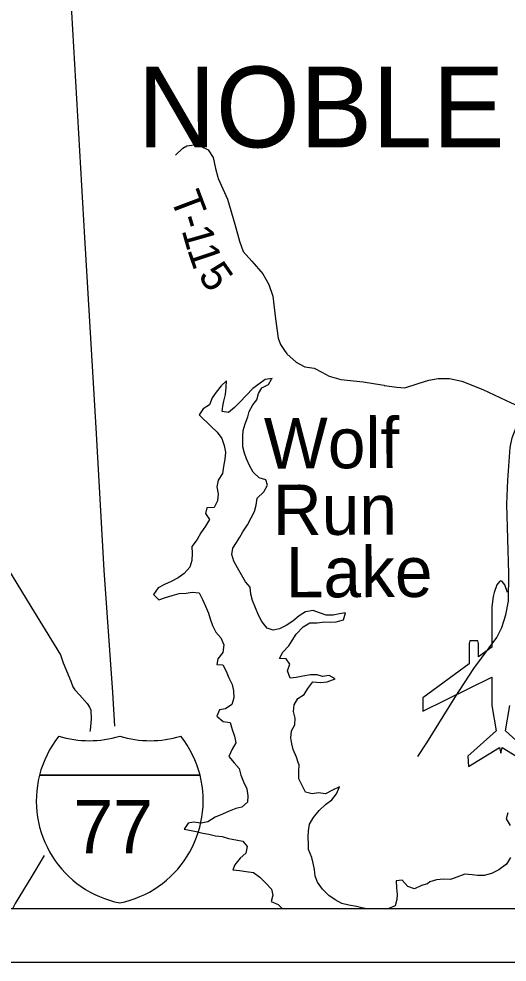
# Model space of a CAD drawing. Extents: x -22 to 431, y -18 to 160.
# Drawn here: x 3.524 to 4.438, y 14 to 15.768 of the extents above; entities that cross this region are included whole.
import ezdxf

# ---------------------------------------------------------------- set-up
doc = ezdxf.new("R2010")
doc.units = 0
for name, color, linetype in [('GM_X_Adjacent_County_Text', 7, 'Continuous'), ('GM_X_Airport_Location_Class_2', 7, 'Continuous'), ('GM_X_Airport_Text_Class_2', 7, 'Continuous'), ('GM_X_City_Street_Text', 7, 'Continuous'), ('GM_X_County_Road', 7, 'Continuous'), ('GM_X_County_Road_Text', 7, 'Continuous'), ('GM_X_Minor_River_Text', 7, 'Continuous'), ('GM_X_Rail_Line', 7, 'Continuous'), ('GM_X_Rail_Line_Text', 7, 'Continuous'), ('GM_X_Section', 7, 'Continuous'), ('GM_X_Township_Subdivision', 7, 'Continuous'), ('GM_X_US_Location', 7, 'Continuous')]:
    doc.layers.add(name, color=color, linetype=linetype)

msp = doc.modelspace()

# ---------------------------------------------------------------- linework, layer by layer
at = {"layer": 'GM_X_Adjacent_County_Text'}
msp.add_lwpolyline([(4.2712, 14.3856), (4.288, 14.4108), (4.341, 14.4966), (4.3758, 14.5505), (4.4185, 14.6086), (4.4283, 14.6269), (4.4359, 14.6508), (4.4404, 14.6766), (4.4411, 14.7286), (4.4376, 14.8583), (4.4394, 14.9035), (4.4439, 14.9642), (4.4477, 14.9824), (4.4552, 15.0022), (4.4628, 15.0181), (4.4707, 15.0352), (4.479, 15.0432), (4.4893, 15.0557), (4.5014, 15.0709), (4.512, 15.0895), (4.5225, 15.1127), (4.5274, 15.1263)], dxfattribs=at)
at = {"layer": 'GM_X_County_Road'}
msp.add_lwpolyline([(3.8174, 15.5124), (3.8309, 15.5254), (3.8388, 15.5296), (3.8521, 15.5316), (3.8653, 15.5287), (3.8786, 15.522), (3.8878, 15.508), (3.8921, 15.4872), (3.8964, 15.4709), (3.8974, 15.4687), (3.8975, 15.4685)], dxfattribs=at)
at = {"layer": 'GM_X_Minor_River_Text'}
for points in [[(3.8975, 15.4685), (3.9145, 15.43), (3.9281, 15.3831), (3.937, 15.3509), (3.944, 15.332), (3.9604, 15.3135), (3.981, 15.2901), (3.9921, 15.2697), (3.9995, 15.2478), (4.0043, 15.2057), (4.0095, 15.1693), (4.0138, 15.1576), (4.02, 15.1484)], [(4.02, 15.1484), (4.0201, 15.1482), (4.0256, 15.1402), (4.0431, 15.1244), (4.0485, 15.1214)], [(4.0485, 15.1214), (4.0487, 15.1213), (4.0591, 15.1154), (4.0769, 15.1133), (4.0914, 15.1058), (4.1047, 15.0979), (4.1271, 15.0917), (4.1687, 15.0878), (4.2036, 15.0816), (4.208, 15.081)], [(4.208, 15.081), (4.2082, 15.0809), (4.2313, 15.0773), (4.2468, 15.0763), (4.2714, 15.0841), (4.2914, 15.0907), (4.3088, 15.0939), (4.3304, 15.0936), (4.3531, 15.0889), (4.3926, 15.0733), (4.4454, 15.0479), (4.4625, 15.0404), (4.4707, 15.0352)], [(3.4447, 14.8728), (3.447, 14.8546), (3.4534, 14.8254), (3.4595, 14.8068), (3.4808, 14.7723), (3.5115, 14.7242), (3.5464, 14.6662), (3.5904, 14.5953), (3.6021, 14.5756), (3.6074, 14.5612), (3.6215, 14.5263), (3.6253, 14.5161), (3.6287, 14.51), (3.6374, 14.5009), (3.6522, 14.485), (3.6566, 14.4777), (3.6586, 14.4725), (3.6598, 14.4554), (3.6575, 14.4346), (3.6568, 14.4321)], [(3.5713, 14.1998), (3.5487, 14.1609), (3.517, 14.11), (3.512, 14.1001)]]:
    msp.add_lwpolyline(points, dxfattribs=at)
at = {"layer": 'GM_X_Rail_Line'}
msp.add_lwpolyline([(3.7036, 14.4423), (3.7002, 14.5056), (3.6838, 14.7345), (3.6691, 15.0011), (3.6475, 15.3581), (3.6235, 15.7804), (3.6085, 16.0371), (3.6062, 16.1206), (3.6079, 16.1719), (3.6138, 16.2179), (3.6292, 16.2658), (3.645, 16.3137), (3.6627, 16.361), (3.6878, 16.4212), (3.7201, 16.4894), (3.7438, 16.5356), (3.7757, 16.6058), (3.8109, 16.6816), (3.8134, 16.6865)], dxfattribs=at)
at = {"layer": 'GM_X_Rail_Line_Text'}
for p, q in [((3.5626, 14.3502), (3.8632, 14.3502)), ((3.8632, 14.3502), (3.5626, 14.3502)), ((3.8632, 14.3502), (3.5626, 14.3502))]:
    msp.add_line(p, q, dxfattribs=at)
for centre, start, end in [((3.752, 14.3023), 141.669, 165.8066), ((3.6559, 14.6103), 253.0091, 286.9909), ((3.77, 14.6103), 253.0091, 286.9909), ((3.6739, 14.3023), 14.1934, 38.331), ((3.752, 14.3023), 165.8066, 258.463), ((3.6739, 14.3023), 281.537, 14.1934)]:
    msp.add_arc(centre, 0.1953, start, end, dxfattribs=at)
at = {"layer": 'GM_X_Section'}
for p, q in [((8.9, 14.1), (2.1, 14.1)), ((2, 14), (9, 14))]:
    msp.add_line(p, q, dxfattribs=at)
at = {"layer": 'GM_X_Township_Subdivision'}
for points in [[(3.9983, 15.0938), (3.9854, 15.0917), (3.9734, 15.0833), (3.9618, 15.0748), (3.9494, 15.0617), (3.9385, 15.0503), (3.9277, 15.0395), (3.9164, 15.0303), (3.905, 15.0321), (3.9061, 15.0416), (3.9078, 15.0511), (3.9111, 15.064), (3.9121, 15.0769), (3.9128, 15.0894), (3.9026, 15.0802), (3.8937, 15.068), (3.8862, 15.0576), (3.881, 15.0447), (3.869, 15.0366), (3.8615, 15.0259), (3.8841, 15.0038), (3.8956, 14.9933), (3.904, 14.9812), (3.9087, 14.9684), (3.9111, 14.9555), (3.9097, 14.9426), (3.9072, 14.9289), (3.9051, 14.916), (3.8969, 14.903), (3.8944, 14.8909), (3.8971, 14.8776), (3.8958, 14.8643), (3.8895, 14.8517), (3.8758, 14.8512), (3.8737, 14.8406), (3.881, 14.8293), (3.8732, 14.817), (3.865, 14.8044), (3.8579, 14.7922), (3.8478, 14.7792), (3.8487, 14.7656), (3.8477, 14.7527), (3.8444, 14.7405), (3.8336, 14.7286), (3.8223, 14.7205), (3.8095, 14.7132), (3.7967, 14.7077), (3.7846, 14.7012), (3.776, 14.6889), (3.786, 14.6788), (3.7988, 14.6835), (3.8113, 14.6874), (3.8245, 14.6906), (3.8373, 14.6915), (3.8487, 14.6931), (3.8616, 14.6921), (3.8681, 14.6793), (3.8736, 14.6669), (3.8794, 14.6537), (3.8821, 14.6431), (3.8868, 14.631), (3.8926, 14.6185), (3.9022, 14.6076), (3.908, 14.5948), (3.9059, 14.5804), (3.8966, 14.5685), (3.8948, 14.5575), (3.9061, 14.5572), (3.9119, 14.5452), (3.9174, 14.5331), (3.9236, 14.5203), (3.9259, 14.5085), (3.9265, 14.4956), (3.9228, 14.4831), (3.9111, 14.475), (3.8994, 14.4726), (3.895, 14.4612), (3.9065, 14.4511), (3.9194, 14.4489), (3.9233, 14.4361), (3.928, 14.4232), (3.93, 14.4107), (3.9233, 14.3989), (3.917, 14.3852), (3.927, 14.3735), (3.9362, 14.3627), (3.9397, 14.3502), (3.9444, 14.3381), (3.9509, 14.3249), (3.9526, 14.3116), (3.952, 14.2995), (3.9418, 14.2907), (3.9305, 14.2879), (3.9177, 14.2832), (3.9052, 14.277), (3.8917, 14.2719), (3.8777, 14.263), (3.8656, 14.2603), (3.8509, 14.262), (3.841, 14.2604), (3.8336, 14.2489)], [(4.0489, 14.3703), (4.0478, 14.3722), (4.0439, 14.3843), (4.0377, 14.3983), (4.0349, 14.4088), (4.0329, 14.4202), (4.0346, 14.4335), (4.0406, 14.4449), (4.0416, 14.4575), (4.0384, 14.4699), (4.0394, 14.4825), (4.0461, 14.4939), (4.0582, 14.5016), (4.0653, 14.5131), (4.0746, 14.5253), (4.0879, 14.5239), (4.1011, 14.5256), (4.1162, 14.5311), (4.1048, 14.5374), (4.0923, 14.535), (4.0828, 14.5387), (4.0699, 14.5382), (4.0559, 14.5361), (4.0435, 14.5333), (4.0317, 14.5321), (4.027, 14.5457), (4.0311, 14.5582), (4.0245, 14.5684), (4.0117, 14.569), (4.018, 14.5812), (4.0292, 14.5927), (4.0355, 14.6026), (4.0434, 14.6149), (4.0565, 14.6283), (4.0685, 14.6356), (4.0825, 14.6358), (4.0962, 14.6378), (4.1083, 14.6372), (4.1181, 14.6377), (4.1317, 14.6412), (4.1357, 14.6545), (4.124, 14.6525), (4.1127, 14.6505), (4.0994, 14.65), (4.0869, 14.6548), (4.0747, 14.6588), (4.0607, 14.6564), (4.0487, 14.649), (4.0367, 14.6387), (4.0243, 14.6306), (4.0122, 14.6244), (4.0001, 14.622), (3.9887, 14.6256), (3.9791, 14.6381), (3.973, 14.6501), (3.9668, 14.6637), (3.9617, 14.6777), (3.9585, 14.6894), (3.9569, 14.703), (3.9485, 14.7128), (3.9411, 14.7256), (3.9334, 14.7388), (3.9265, 14.7513), (3.9226, 14.7637), (3.9247, 14.7755), (3.9314, 14.7862), (3.9377, 14.7961), (3.9433, 14.8061), (3.9523, 14.8198), (3.959, 14.8328), (3.9653, 14.8442), (3.9686, 14.8564), (3.9699, 14.8693), (3.9827, 14.8816), (3.9898, 14.8938), (3.9866, 14.904), (3.9741, 14.9073), (3.9626, 14.9181), (3.9557, 14.931), (3.9502, 14.9434), (3.9463, 14.9536), (3.9436, 14.9657), (3.9431, 14.9756), (3.9434, 14.9854), (3.944, 14.9961), (3.9477, 15.009), (3.9525, 15.022), (3.955, 15.0318), (3.9621, 15.0441), (3.9695, 15.0536), (3.9725, 15.0654), (3.9792, 15.0765), (3.9912, 15.0823), (3.9972, 15.0926), (3.9983, 15.0938)], [(4.1755, 14.1), (4.166, 14.102), (4.1558, 14.1042), (4.1418, 14.1067), (4.1285, 14.1099), (4.1163, 14.117), (4.1041, 14.1248), (4.0926, 14.1368), (4.0834, 14.1496), (4.0787, 14.161), (4.0775, 14.1738), (4.0747, 14.1856), (4.0727, 14.1958), (4.0661, 14.2109), (4.066, 14.2211), (4.0655, 14.234), (4.0665, 14.2461), (4.0683, 14.2583), (4.0757, 14.2713), (4.0862, 14.2839), (4.0982, 14.2954), (4.1098, 14.3039), (4.1188, 14.3153), (4.1243, 14.3283), (4.1115, 14.3221), (4.0983, 14.3151), (4.0851, 14.3172), (4.073, 14.3156), (4.0608, 14.3185), (4.0546, 14.3313), (4.0484, 14.3434), (4.0483, 14.3567), (4.0489, 14.3703)], [(4.4395, 14.2801), (4.4362, 14.2684), (4.4439, 14.2559)], [(3.8336, 14.2489), (3.8438, 14.2475), (3.8563, 14.2446), (3.8685, 14.2417), (3.8799, 14.2396), (3.892, 14.2367), (3.9045, 14.2353), (3.9167, 14.232), (3.93, 14.2291), (3.9436, 14.2266), (3.9517, 14.2168), (3.9488, 14.2043), (3.9383, 14.1947), (3.9285, 14.1825), (3.9245, 14.1729), (3.9374, 14.1716), (3.9495, 14.1698), (3.9632, 14.168), (3.975, 14.1591), (3.9868, 14.1474), (3.9968, 14.1366), (3.9996, 14.1252), (3.9963, 14.1134), (4.0096, 14.1079), (4.0179, 14.1)], [(4.4445, 14.1964), (4.4367, 14.1834), (4.4224, 14.173), (4.4089, 14.1661), (4.3953, 14.1621), (4.3824, 14.1624), (4.3725, 14.1634), (4.3589, 14.1648), (4.3442, 14.1593), (4.3321, 14.155), (4.3196, 14.1552), (4.306, 14.1543), (4.2932, 14.1508)], [(4.2932, 14.1508), (4.289, 14.1469), (4.2777, 14.1434), (4.2645, 14.1372), (4.2524, 14.1416), (4.2416, 14.1536), (4.2303, 14.1524), (4.2312, 14.1395), (4.2321, 14.127), (4.2314, 14.1175), (4.2285, 14.1053), (4.2164, 14.1003), (4.2147, 14.1)]]:
    msp.add_lwpolyline(points, dxfattribs=at)
at = {"layer": 'GM_X_US_Location'}
for points in [[(4.4387, 14.6926), (4.4336, 14.7072), (4.4289, 14.7136), (4.4262, 14.7147), (4.4235, 14.7136), (4.4188, 14.7072), (4.4137, 14.6926), (4.4116, 14.6855), (4.4091, 14.6656), (4.4091, 14.5903), (4.3843, 14.572), (4.3843, 14.5972), (4.383, 14.6019), (4.3683, 14.6019), (4.3669, 14.5972), (4.3669, 14.5591), (4.2805, 14.4952), (4.2805, 14.4706), (4.4091, 14.534), (4.4091, 14.4807), (4.4176, 14.4334), (4.3647, 14.386), (4.3655, 14.3664), (4.4235, 14.4023), (4.4262, 14.3918), (4.4289, 14.4023), (4.4868, 14.3664)], [(4.4876, 14.386), (4.4347, 14.4334), (4.4433, 14.4807)]]:
    msp.add_lwpolyline(points, dxfattribs=at)

# ---------------------------------------------------------------- texts
at = {"layer": 'GM_X_Airport_Location_Class_2'}
msp.add_text('77', height=0.1, dxfattribs=at).set_placement((3.6262, 14.2039))
at = {"layer": 'GM_X_Airport_Text_Class_2'}
for s, rotation, p in [('Wolf', 0.2496, (3.9831, 14.9249)), ('Run', 0.2492, (3.9997, 14.8002)), ('Lake', 0.2482, (4.024, 14.6833))]:
    msp.add_text(s, height=0.0947, rotation=rotation, dxfattribs=at).set_placement(p)
at = {"layer": 'GM_X_City_Street_Text'}
for s, rotation, p in [('T', 290.7055, (3.807, 15.4327)), ('-', 286.9759, (3.8217, 15.3939)), ('1', 285.9361, (3.8285, 15.3718)), ('1', 288.6406, (3.8389, 15.3354)), ('5', 304.9988, (3.8581, 15.2865))]:
    msp.add_text(s, height=0.0568, rotation=rotation, dxfattribs=at).set_placement(p)
at = {"layer": 'GM_X_County_Road_Text'}
msp.add_text('NOBLE', height=0.15152, rotation=0, dxfattribs=at).set_placement((3.7463, 15.5269))

doc.saveas('drawing.dxf')
